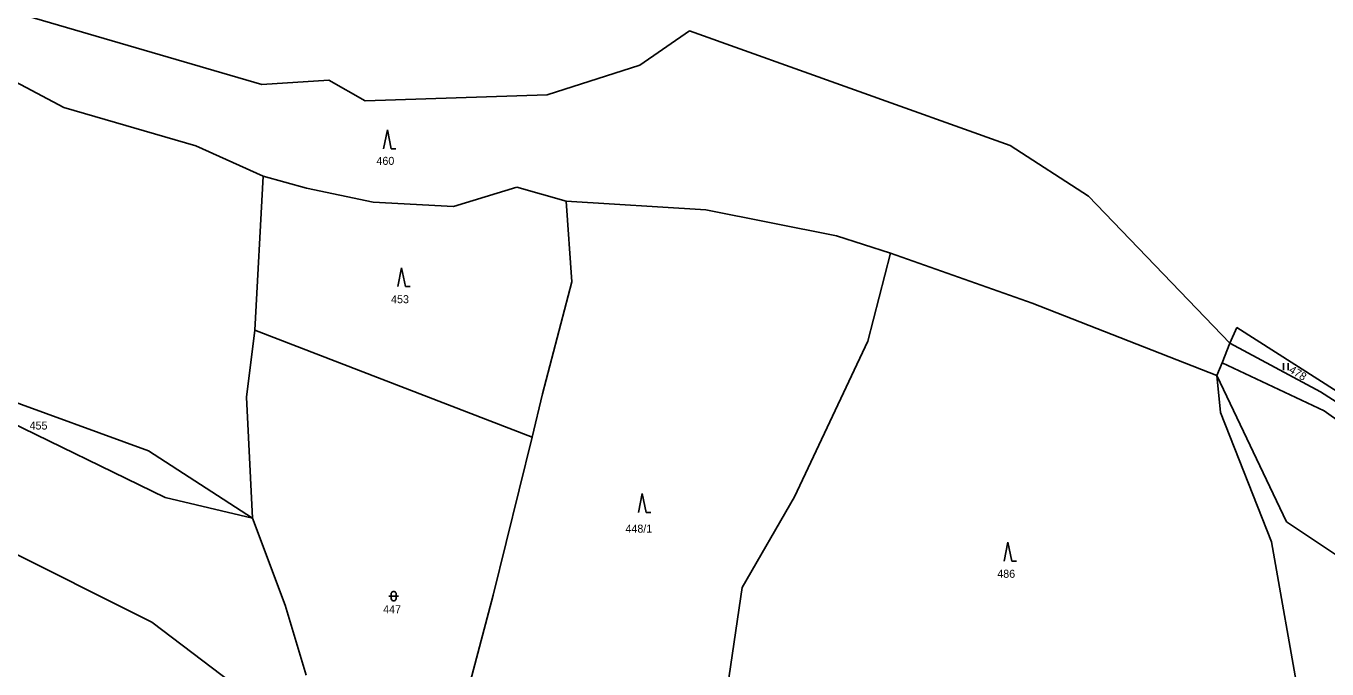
# Model space of a CAD drawing. Extents: x -794421 to -792735, y -1117671 to -1115559.
# Drawn here: x -793818.1 to -793541.7, y -1116832.7 to -1116696.2 of the extents above; entities that cross this region are included whole.
import ezdxf

# ---------------------------------------------------------------- set-up
doc = ezdxf.new("R2010")
doc.units = 0
for name, color, linetype in [('Vrstva 1', 7, 'Continuous'), ('Vrstva 14', 7, 'Continuous'), ('Vrstva 23', 7, 'Continuous')]:
    doc.layers.add(name, color=color, linetype=linetype)

msp = doc.modelspace()

# ---------------------------------------------------------------- linework, layer by layer
at = {"layer": 'Vrstva 1'}
for p, q in [((-793817.93, -1116694.07), (-793767.94, -1116708.64)), ((-793687.65, -1116704.53), (-793677.13, -1116697.26)), ((-793677.13, -1116697.26), (-793608.99, -1116721.57)), ((-793707.37, -1116710.85), (-793687.65, -1116704.53)), ((-793821.53, -1116707.45), (-793810.02, -1116713.5)), ((-793767.94, -1116708.64), (-793753.71, -1116707.72)), ((-793753.71, -1116707.72), (-793746.04, -1116712.11)), ((-793746.04, -1116712.11), (-793707.37, -1116710.85)), ((-793810.02, -1116713.5), (-793781.99, -1116721.68)), ((-793781.99, -1116721.68), (-793767.69, -1116728.09)), ((-793608.99, -1116721.57), (-793592.41, -1116732.32)), ((-793769.45, -1116760.82), (-793767.69, -1116728.09)), ((-793767.69, -1116728.09), (-793758.5, -1116730.64)), ((-793758.5, -1116730.64), (-793744.3, -1116733.64)), ((-793727.28, -1116734.55), (-793713.81, -1116730.46)), ((-793713.81, -1116730.46), (-793703.31, -1116733.43)), ((-793744.3, -1116733.64), (-793727.28, -1116734.55)), ((-793703.31, -1116733.43), (-793673.63, -1116735.23)), ((-793702.15, -1116750.57), (-793703.31, -1116733.43)), ((-793592.41, -1116732.32), (-793562.36, -1116763.54)), ((-793673.63, -1116735.23), (-793645.92, -1116740.79)), ((-793645.92, -1116740.79), (-793634.44, -1116744.47)), ((-793634.44, -1116744.47), (-793639.28, -1116763.1)), ((-793604.38, -1116755.1), (-793634.44, -1116744.47)), ((-793708.35, -1116774.35), (-793702.15, -1116750.57)), ((-793565.1, -1116770.45), (-793604.38, -1116755.1)), ((-793771.2, -1116775.02), (-793769.45, -1116760.82)), ((-793769.45, -1116760.82), (-793710.57, -1116783.51)), ((-793560.85, -1116760.22), (-793562.36, -1116763.54)), ((-793560.85, -1116760.22), (-793529.97, -1116779.96)), ((-793639.28, -1116763.1), (-793654.8, -1116796.19)), ((-793562.36, -1116763.54), (-793564.01, -1116767.7)), ((-793562.36, -1116763.54), (-793543.13, -1116773.91)), ((-793792.05, -1116786.44), (-793839.76, -1116769.02)), ((-793564.01, -1116767.7), (-793565.1, -1116770.45)), ((-793542.35, -1116777.91), (-793564.01, -1116767.7)), ((-793840.38, -1116771.07), (-793788.52, -1116796.32)), ((-793565.1, -1116770.45), (-793550.33, -1116801.48)), ((-793564.33, -1116778.31), (-793565.1, -1116770.45)), ((-793769.94, -1116800.69), (-793771.2, -1116775.02)), ((-793710.57, -1116783.51), (-793708.35, -1116774.35)), ((-793543.13, -1116773.91), (-793531.13, -1116781.55)), ((-793553.49, -1116805.76), (-793564.33, -1116778.31)), ((-793542.35, -1116777.91), (-793495.16, -1116811.62)), ((-793710.57, -1116783.51), (-793718.86, -1116817.08)), ((-793769.94, -1116800.69), (-793792.05, -1116786.44)), ((-793788.52, -1116796.32), (-793769.94, -1116800.69)), ((-793654.8, -1116796.19), (-793665.98, -1116815.45)), ((-793791.34, -1116822.79), (-793839.07, -1116798.91)), ((-793763.02, -1116819.17), (-793769.94, -1116800.69)), ((-793550.33, -1116801.48), (-793505.53, -1116831.44)), ((-793547.25, -1116841.03), (-793553.49, -1116805.76)), ((-793665.98, -1116815.45), (-793669.58, -1116840)), ((-793758.53, -1116834.02), (-793763.02, -1116819.17)), ((-793718.86, -1116817.08), (-793724.75, -1116839.35)), ((-793757.25, -1116848.58), (-793791.34, -1116822.79))]:
    msp.add_line(p, q, dxfattribs=at)
at = {"layer": 'Vrstva 23'}
for p, q in [((-793742.11, -1116722.29), (-793741.31, -1116718.29)), ((-793741.31, -1116718.29), (-793740.51, -1116722.29)), ((-793740.51, -1116722.29), (-793739.51, -1116722.29)), ((-793739.09, -1116751.54), (-793738.29, -1116747.54)), ((-793738.29, -1116747.54), (-793737.49, -1116751.54)), ((-793737.49, -1116751.54), (-793736.49, -1116751.54)), ((-793550.96, -1116769.32), (-793550.96, -1116767.82)), ((-793549.96, -1116767.82), (-793549.96, -1116769.32)), ((-793687.96, -1116799.48), (-793687.16, -1116795.48)), ((-793687.16, -1116795.48), (-793686.36, -1116799.48)), ((-793686.36, -1116799.48), (-793685.36, -1116799.48)), ((-793610.3, -1116809.81), (-793609.5, -1116805.81)), ((-793609.5, -1116805.81), (-793608.7, -1116809.81)), ((-793608.7, -1116809.81), (-793607.7, -1116809.81)), ((-793740.47, -1116816.66), (-793740.37, -1116816.46)), ((-793740.47, -1116817.86), (-793740.47, -1116816.66)), ((-793740.37, -1116816.46), (-793740.27, -1116816.36)), ((-793740.27, -1116816.36), (-793740.07, -1116816.26)), ((-793740.07, -1116816.26), (-793739.87, -1116816.26)), ((-793739.87, -1116816.26), (-793739.67, -1116816.36)), ((-793739.67, -1116816.36), (-793739.57, -1116816.46)), ((-793739.57, -1116816.46), (-793739.47, -1116816.66)), ((-793739.47, -1116816.66), (-793739.47, -1116817.86)), ((-793740.97, -1116817.26), (-793738.97, -1116817.26)), ((-793740.37, -1116818.06), (-793740.47, -1116817.86)), ((-793740.27, -1116818.16), (-793740.37, -1116818.06)), ((-793740.07, -1116818.26), (-793740.27, -1116818.16)), ((-793739.87, -1116818.26), (-793740.07, -1116818.26)), ((-793739.67, -1116818.16), (-793739.87, -1116818.26)), ((-793739.57, -1116818.06), (-793739.67, -1116818.16)), ((-793739.47, -1116817.86), (-793739.57, -1116818.06))]:
    msp.add_line(p, q, dxfattribs=at)

# ---------------------------------------------------------------- texts
at = {"layer": 'Vrstva 14'}
for s, p in [('460', (-793743.632, -1116725.7)), ('453', (-793740.519, -1116755.07)), ('455', (-793817.305, -1116781.9)), ('448/1', (-793690.735, -1116803.79)), ('486', (-793611.762, -1116813.37)), ('447', (-793742.205, -1116820.91))]:
    msp.add_text(s, height=1.7, dxfattribs=at).set_placement(p)
msp.add_text('478', height=1.7, rotation=328.4127, dxfattribs=at).set_placement((-793549.969, -1116769.642))

doc.saveas('drawing.dxf')
